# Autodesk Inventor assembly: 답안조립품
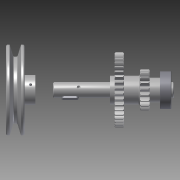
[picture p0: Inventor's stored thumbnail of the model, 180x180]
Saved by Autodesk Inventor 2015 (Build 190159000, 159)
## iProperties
Created: 2015-09
Part Number: 답안조립품
Document SubType Name: Assembly
Designer: PHO-02
Author: PHO-02
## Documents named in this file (9)
- C:\Users\PHO-02\Desktop\450907V1028\답안조립품.iam
- C:\Users\PHO-02\Desktop\450907V1028\본체.ipt
- C:\Users\PHO-02\Desktop\450907V1028\뒤커버.ipt
- C:\Users\PHO-02\Desktop\450907V1028\베어링 6203.ipt
- C:\Users\PHO-02\Desktop\450907V1028\축.ipt
- C:\Users\PHO-02\Desktop\450907V1028\키 - 6 x 6 x 22.ipt
- C:\Users\PHO-02\Desktop\450907V1028\스퍼기어.ipt
- C:\Users\PHO-02\Desktop\450907V1028\키 - 5 x 5 x 18.ipt
- C:\Users\PHO-02\Desktop\450907V1028\V-벨트풀리.ipt
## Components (1 placed, 1 different names)
1. V-벨트풀리:1
